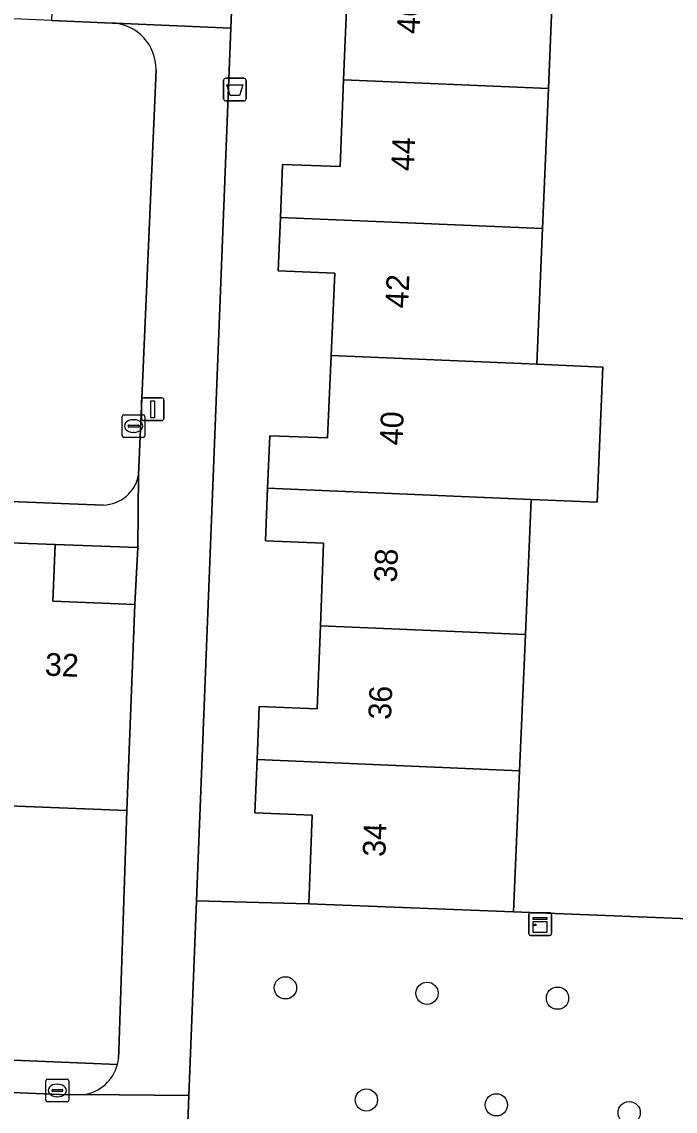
# Model space of a CAD drawing. Extents: x 160786 to 161429, y 386828 to 387485.
# Drawn here: x 161097.07 to 161125.82, y 387264.64 to 387312.56 of the extents above; entities that cross this region are included whole.
import ezdxf

# ---------------------------------------------------------------- set-up
doc = ezdxf.new("R2010")
doc.units = 0
for name, color, linetype in [('IMGEO_Afvalbak', 7, 'Continuous'), ('IMGEO_Boom', 7, 'Continuous'), ('IMGEO_Erf', 7, 'Continuous'), ('IMGEO_Groenvoorziening', 7, 'Continuous'), ('IMGEO_Kast', 7, 'Continuous'), ('IMGEO_Kolk', 7, 'Continuous'), ('IMGEO_Lichtmast', 7, 'Continuous'), ('IMGEO_Pand', 7, 'Continuous'), ('IMGEO_Pand_nummerreeks', 7, 'Continuous'), ('IMGEO_Rioolput', 7, 'Continuous'), ('IMGEO_Voetpad_open', 7, 'Continuous')]:
    doc.layers.add(name, color=color, linetype=linetype)

msp = doc.modelspace()

# ---------------------------------------------------------------- linework, layer by layer
at = {"layer": 'IMGEO_Afvalbak'}
for p, q in [((161105.946, 387309.18), (161105.946, 387309.98)), ((161105.946, 387309.98), (161105.946, 387309.18)), ((161106.046, 387310.08), (161106.836, 387310.08)), ((161106.836, 387310.08), (161106.046, 387310.08)), ((161106.936, 387309.98), (161106.936, 387309.18)), ((161106.936, 387309.18), (161106.936, 387309.98)), ((161106.836, 387309.08), (161106.046, 387309.08)), ((161106.046, 387309.08), (161106.836, 387309.08))]:
    msp.add_line(p, q, dxfattribs=at)
msp.add_lwpolyline([(161106.089, 387309.794), (161106.793, 387309.794), (161106.644, 387309.324), (161106.238, 387309.324), (161106.089, 387309.794)], dxfattribs=at)
for centre, start, end in [((161106.046, 387309.98), 90, 180), ((161106.046, 387309.98), 90, 180), ((161106.836, 387309.98), 0, 90), ((161106.836, 387309.98), 360, 90), ((161106.046, 387309.18), 180, 270), ((161106.046, 387309.18), 180, 270), ((161106.836, 387309.18), 270, 0), ((161106.836, 387309.18), 270, 0)]:
    msp.add_arc(centre, 0.1, start, end, dxfattribs=at)
at = {"layer": 'IMGEO_Boom'}
for centre in [(161108.67, 387270.067), (161114.902, 387269.831), (161120.638, 387269.615), (161112.233, 387265.138), (161117.951, 387264.922), (161123.79, 387264.578)]:
    msp.add_circle(centre, 0.489, dxfattribs=at)
at = {"layer": 'IMGEO_Erf'}
for points in [[(161107.845, 387352.38), (161106.267, 387312.29), (161104.756, 387273.893), (161109.694, 387273.762), (161109.847, 387277.67), (161107.328, 387277.768), (161107.42, 387280.108), (161107.511, 387282.445), (161110.065, 387282.345), (161110.208, 387285.99), (161110.35, 387289.634), (161107.795, 387289.734), (161107.885, 387292.045), (161107.976, 387294.356), (161110.526, 387294.256), (161110.687, 387297.88), (161110.848, 387301.503), (161108.353, 387301.603), (161108.448, 387303.95), (161108.542, 387306.293), (161111.074, 387306.191), (161111.228, 387310.015), (161111.382, 387313.838)], [(161133.977, 387351.235), (161125.69, 387351.675), (161125.432, 387345.543), (161121.755, 387345.698), (161121.504, 387339.734), (161121.251, 387333.744), (161120.996, 387327.673), (161120.743, 387321.672), (161120.493, 387315.737), (161120.236, 387309.635), (161119.976, 387303.464), (161119.725, 387297.499), (161122.627, 387297.377), (161122.377, 387291.435), (161119.474, 387291.557), (161119.224, 387285.61), (161118.972, 387279.621), (161118.71, 387273.409), (161130.826, 387272.934)], [(161101.692, 387277.875), (161095.739, 387278.107), (161089.782, 387278.339), (161083.812, 387278.572), (161077.787, 387278.807), (161071.808, 387279.04), (161065.781, 387279.275), (161059.712, 387279.512), (161053.612, 387279.75), (161047.514, 387279.988), (161041.541, 387280.221), (161035.537, 387280.455), (161035.313, 387280.464), (161035.188, 387277.258), (161029.377, 387277.484), (161029.502, 387280.69), (161023.521, 387280.923), (161017.529, 387281.157), (161011.527, 387281.391), (161011.389, 387277.862), (161005.238, 387278.102), (161005.045, 387271.345)], [(161101.327, 387266.961), (161101.339, 387267.305), (161101.692, 387277.875)], [(161091.074, 387267.115), (161101.28, 387266.701)]]:
    msp.add_lwpolyline(points, dxfattribs=at)
msp.add_lwpolyline([(161098.533, 387289.573), (161098.436, 387287.071), (161102.045, 387286.93), (161102.179, 387289.436)], close=True, dxfattribs=at)
msp.add_arc((161099.442, 387267.168), 1.897, 345.7595, 353.7471, dxfattribs=at)
at = {"layer": 'IMGEO_Groenvoorziening'}
for points in [[(161132.146, 387273.388), (161130.846, 387273.44), (161130.826, 387272.934), (161118.71, 387273.409), (161109.694, 387273.762), (161104.756, 387273.893), (161104.419, 387265.337), (161104.372, 387264.144)], [(161090.777, 387267.127), (161090.728, 387265.863), (161090.722, 387265.707), (161099.086, 387265.364), (161099.828, 387265.381)], [(161101.28, 387266.701), (161091.074, 387267.115), (161090.777, 387267.127)]]:
    msp.add_lwpolyline(points, dxfattribs=at)
msp.add_arc((161099.547, 387267.148), 1.79, 279.0246, 345.5228, dxfattribs=at)
at = {"layer": 'IMGEO_Kast'}
for p, q in [((161119.377, 387272.447), (161119.377, 387273.288)), ((161119.377, 387273.288), (161119.377, 387272.447)), ((161119.452, 387273.372), (161120.293, 387273.372)), ((161120.293, 387273.372), (161119.452, 387273.372)), ((161120.377, 387273.297), (161120.377, 387272.456)), ((161120.377, 387272.456), (161120.377, 387273.297)), ((161120.302, 387272.372), (161119.461, 387272.372)), ((161119.461, 387272.372), (161120.302, 387272.372))]:
    msp.add_line(p, q, dxfattribs=at)
for points in [[(161119.572, 387273.162), (161120.172, 387273.162), (161120.172, 387273.077), (161119.572, 387273.077), (161119.572, 387273.162)], [(161119.572, 387272.987), (161120.172, 387272.987), (161120.172, 387272.498), (161119.572, 387272.498), (161119.572, 387272.987)]]:
    msp.add_lwpolyline(points, dxfattribs=at)
msp.add_circle((161119.656, 387272.836), 0.0377, dxfattribs=at)
for centre, start, end in [((161119.455, 387273.294), 92.4484, 184.2845), ((161119.455, 387273.294), 92.4484, 184.2845), ((161120.299, 387273.294), 2.4484, 94.2845), ((161120.299, 387273.294), 2.4484, 94.2845), ((161119.455, 387272.45), 182.4484, 274.2845), ((161119.455, 387272.45), 182.4484, 274.2845), ((161120.299, 387272.45), 272.4484, 4.2845), ((161120.299, 387272.45), 272.4484, 4.2845)]:
    msp.add_arc(centre, 0.0779, start, end, dxfattribs=at)
at = {"layer": 'IMGEO_Kolk'}
for p, q in [((161098.209, 387266.053), (161099.061, 387266.053)), ((161098.134, 387265.127), (161098.134, 387265.979)), ((161098.393, 387265.547), (161098.393, 387265.559)), ((161098.436, 387265.596), (161098.834, 387265.596)), ((161098.622, 387265.833), (161098.647, 387265.833)), ((161098.877, 387265.559), (161098.877, 387265.547)), ((161099.135, 387265.979), (161099.135, 387265.127)), ((161098.831, 387265.51), (161098.433, 387265.51)), ((161098.645, 387265.273), (161098.62, 387265.273)), ((161099.061, 387265.053), (161098.209, 387265.053))]:
    msp.add_line(p, q, dxfattribs=at)
for points in [[(161098.209, 387266.053), (161099.061, 387266.053)], [(161098.134, 387265.127), (161098.134, 387265.979)], [(161099.135, 387265.979), (161099.135, 387265.127)], [(161099.061, 387265.053), (161098.209, 387265.053)]]:
    msp.add_lwpolyline(points, dxfattribs=at)
for centre, radius, start, end in [((161098.211, 387265.977), 0.0765, 91.552, 178.448), ((161098.211, 387265.977), 0.0765, 91.552, 178.448), ((161099.059, 387265.977), 0.0765, 1.552, 88.448), ((161099.059, 387265.977), 0.0765, 1.552, 88.448), ((161098.433, 387265.556), 0.0403, 85.8775, 175.7526), ((161098.838, 387265.558), 0.0386, 1.7309, 96.639), ((161098.211, 387265.129), 0.0765, 181.552, 268.448), ((161098.211, 387265.129), 0.0765, 181.552, 268.448), ((161098.43, 387265.546), 0.0366, 178.938, 274.7102), ((161098.834, 387265.553), 0.043, 264.8664, 352.4533), ((161099.059, 387265.129), 0.0765, 271.552, 358.448), ((161099.059, 387265.129), 0.0765, 271.552, 358.448)]:
    msp.add_arc(centre, radius, start, end, dxfattribs=at)
for centre, major_axis, ratio, start_param, end_param in [((161098.621, 387265.553), (-0.387, 0.002), 0.722429, 4.712389, 7.853982), ((161098.646, 387265.553), (-0.39, 0.002), 0.717154, 1.570796, 4.712389)]:
    msp.add_ellipse(centre, major_axis=major_axis, ratio=ratio, start_param=start_param, end_param=end_param, dxfattribs=at)
at = {"layer": 'IMGEO_Lichtmast'}
for p, q in [((161102.333, 387295.121), (161102.333, 387295.921)), ((161102.333, 387295.921), (161102.333, 387295.121)), ((161102.433, 387296.021), (161103.223, 387296.021)), ((161103.223, 387296.021), (161102.433, 387296.021)), ((161103.323, 387295.921), (161103.323, 387295.121)), ((161103.323, 387295.121), (161103.323, 387295.921)), ((161103.223, 387295.021), (161102.433, 387295.021)), ((161102.433, 387295.021), (161103.223, 387295.021))]:
    msp.add_line(p, q, dxfattribs=at)
msp.add_lwpolyline([(161102.753, 387295.896), (161102.903, 387295.896), (161102.903, 387295.146), (161102.753, 387295.146), (161102.753, 387295.896)], dxfattribs=at)
for centre, start, end in [((161102.433, 387295.921), 90, 180), ((161102.433, 387295.921), 90, 180), ((161103.223, 387295.921), 0, 90), ((161103.223, 387295.921), 360, 90), ((161102.433, 387295.121), 180, 270), ((161102.433, 387295.121), 180, 270), ((161103.223, 387295.121), 270, 0), ((161103.223, 387295.121), 270, 0)]:
    msp.add_arc(centre, 0.1, start, end, dxfattribs=at)
at = {"layer": 'IMGEO_Pand'}
for points in [[(161108.982, 387316.222), (161108.89, 387313.938), (161111.382, 387313.838), (161111.228, 387310.015), (161120.236, 387309.635), (161120.493, 387315.737)], [(161119.976, 387303.464), (161120.236, 387309.635), (161111.228, 387310.015), (161111.074, 387306.191), (161108.542, 387306.293), (161108.448, 387303.95)], [(161119.725, 387297.499), (161119.976, 387303.464), (161108.448, 387303.95), (161108.353, 387301.603), (161110.848, 387301.503), (161110.687, 387297.88)], [(161119.725, 387297.499), (161110.687, 387297.88), (161110.526, 387294.256), (161107.976, 387294.356), (161107.885, 387292.045), (161119.474, 387291.557), (161122.377, 387291.435), (161122.627, 387297.377)], [(161107.885, 387292.045), (161107.795, 387289.734), (161110.35, 387289.634), (161110.208, 387285.99), (161119.224, 387285.61), (161119.474, 387291.557)], [(161102.045, 387286.93), (161098.436, 387287.071), (161098.533, 387289.573), (161096.19, 387289.665), (161095.739, 387278.107), (161101.692, 387277.875)], [(161118.972, 387279.621), (161119.224, 387285.61), (161110.208, 387285.99), (161110.065, 387282.345), (161107.511, 387282.445), (161107.42, 387280.108)], [(161107.42, 387280.108), (161107.328, 387277.768), (161109.847, 387277.67), (161109.694, 387273.762), (161118.71, 387273.409), (161118.972, 387279.621)]]:
    msp.add_lwpolyline(points, close=True, dxfattribs=at)
at = {"layer": 'IMGEO_Rioolput'}
for p, q in [((161101.563, 387295.28), (161102.415, 387295.28)), ((161101.488, 387294.354), (161101.488, 387295.206)), ((161101.79, 387294.823), (161102.188, 387294.823)), ((161101.976, 387295.06), (161102.001, 387295.06)), ((161102.489, 387295.206), (161102.489, 387294.354)), ((161101.747, 387294.774), (161101.747, 387294.786)), ((161102.185, 387294.737), (161101.787, 387294.737)), ((161101.999, 387294.5), (161101.974, 387294.5)), ((161102.231, 387294.786), (161102.231, 387294.774)), ((161102.415, 387294.28), (161101.563, 387294.28))]:
    msp.add_line(p, q, dxfattribs=at)
for points in [[(161101.563, 387295.28), (161102.415, 387295.28)], [(161101.488, 387294.354), (161101.488, 387295.206)], [(161102.489, 387295.206), (161102.489, 387294.354)], [(161102.415, 387294.28), (161101.563, 387294.28)]]:
    msp.add_lwpolyline(points, dxfattribs=at)
for centre, radius, start, end in [((161101.565, 387295.204), 0.0765, 91.552, 178.448), ((161101.565, 387295.204), 0.0765, 91.552, 178.448), ((161102.413, 387295.204), 0.0765, 1.552, 88.448), ((161102.413, 387295.204), 0.0765, 1.552, 88.448), ((161101.787, 387294.783), 0.0403, 85.8775, 175.7526), ((161102.192, 387294.785), 0.0386, 1.7309, 96.639), ((161101.565, 387294.356), 0.0765, 181.552, 268.448), ((161101.565, 387294.356), 0.0765, 181.552, 268.448), ((161101.784, 387294.773), 0.0366, 178.938, 274.7102), ((161102.188, 387294.78), 0.043, 264.8664, 352.4533), ((161102.413, 387294.356), 0.0765, 271.552, 358.448), ((161102.413, 387294.356), 0.0765, 271.552, 358.448)]:
    msp.add_arc(centre, radius, start, end, dxfattribs=at)
for centre, major_axis, ratio, start_param, end_param in [((161101.975, 387294.78), (-0.387, 0.002), 0.722429, 4.712389, 7.853982), ((161102, 387294.78), (-0.39, 0.002), 0.717154, 1.570796, 4.712389)]:
    msp.add_ellipse(centre, major_axis=major_axis, ratio=ratio, start_param=start_param, end_param=end_param, dxfattribs=at)
at = {"layer": 'IMGEO_Voetpad_open'}
msp.add_lwpolyline([(161107.845, 387352.38), (161100.034, 387352.72), (161099.864, 387348.657), (161099.582, 387341.538), (161099.408, 387337.356), (161099.097, 387330.241), (161098.923, 387326.08), (161098.631, 387318.661), (161098.379, 387312.62), (161101.064, 387312.508), (161101.196, 387312.508), (161106.267, 387312.29)], close=True, dxfattribs=at)
for points in [[(161101.064, 387312.508), (161098.379, 387312.62), (161095.312, 387312.75), (161092.245, 387312.879), (161089.178, 387313.009), (161086.111, 387313.138), (161083.043, 387313.268), (161079.976, 387313.398), (161076.909, 387313.527), (161073.842, 387313.657), (161068.329, 387313.841), (161065.257, 387313.973), (161062.185, 387314.105), (161059.113, 387314.237), (161056.042, 387314.368), (161052.97, 387314.5), (161049.898, 387314.632), (161046.826, 387314.764), (161043.754, 387314.896), (161043.36, 387301.265)], [(161099.828, 387265.381), (161104.419, 387265.337), (161104.756, 387273.893), (161106.267, 387312.29)], [(161106.267, 387312.29), (161101.196, 387312.508), (161101.064, 387312.508)], [(161102.976, 387310.447), (161102.212, 387292.628), (161102.179, 387289.436), (161102.045, 387286.93), (161101.692, 387277.875), (161101.339, 387267.305), (161101.327, 387266.961)], [(161102.212, 387292.628), (161102.976, 387310.447)], [(161041.191, 387299.617), (161033.89, 387299.928), (161033.794, 387299.932), (161033.563, 387294.053), (161033.559, 387293.946), (161100.662, 387291.305)], [(161100.662, 387291.305), (161033.559, 387293.946), (161030.833, 387294.053)], [(161038.374, 387292.034), (161045.615, 387291.726), (161047.968, 387291.634), (161050.318, 387291.542), (161057.814, 387291.229), (161060.165, 387291.137), (161062.516, 387291.045), (161069.952, 387290.729), (161072.26, 387290.639), (161074.568, 387290.549), (161081.915, 387290.273), (161084.265, 387290.182), (161086.617, 387290.09), (161093.847, 387289.756), (161096.19, 387289.665), (161098.533, 387289.573), (161102.179, 387289.436), (161102.212, 387292.628)], [(161104.687, 387263.019), (161104.6, 387263.164), (161104.526, 387263.317), (161104.465, 387263.476), (161104.42, 387263.639), (161104.389, 387263.806), (161104.373, 387263.974), (161104.372, 387264.144), (161104.419, 387265.337), (161099.828, 387265.381), (161099.086, 387265.364), (161090.722, 387265.707), (161086.994, 387265.86), (161078.768, 387266.198), (161074.828, 387266.36), (161067.122, 387266.676), (161062.922, 387266.848), (161055, 387267.174), (161054.965, 387267.213), (161050.837, 387267.344), (161042.15, 387267.701), (161042.242, 387259.789), (161042.243, 387259.778)]]:
    msp.add_lwpolyline(points, dxfattribs=at)
for centre, radius, start, end in [((161100.953, 387310.487), 2.024, 358.8545, 86.85), ((161100.953, 387310.487), 2.024, 358.8545, 86.85), ((161100.618, 387292.926), 1.621, 271.5467, 349.418), ((161100.618, 387292.926), 1.621, 271.5467, 349.418), ((161099.547, 387267.148), 1.79, 279.0246, 345.5228), ((161099.442, 387267.168), 1.897, 345.7595, 353.7471)]:
    msp.add_arc(centre, radius, start, end, dxfattribs=at)

# ---------------------------------------------------------------- texts
at = {"layer": 'IMGEO_Pand_nummerreeks'}
for s, rotation, p in [('46', 87.6236, (161114.564, 387312.017)), ('44', 87.6236, (161114.314, 387305.983)), ('42', 87.6236, (161114.063, 387299.947)), ('40', 87.6224, (161113.814, 387293.92)), ('38', 87.6236, (161113.563, 387287.887)), ('32', 357.7109, (161098.075, 387283.806)), ('36', 87.6236, (161113.312, 387281.851)), ('34', 87.6236, (161113.062, 387275.817))]:
    msp.add_text(s, height=1, rotation=rotation, dxfattribs=at).set_placement(p)

doc.saveas('drawing.dxf')
